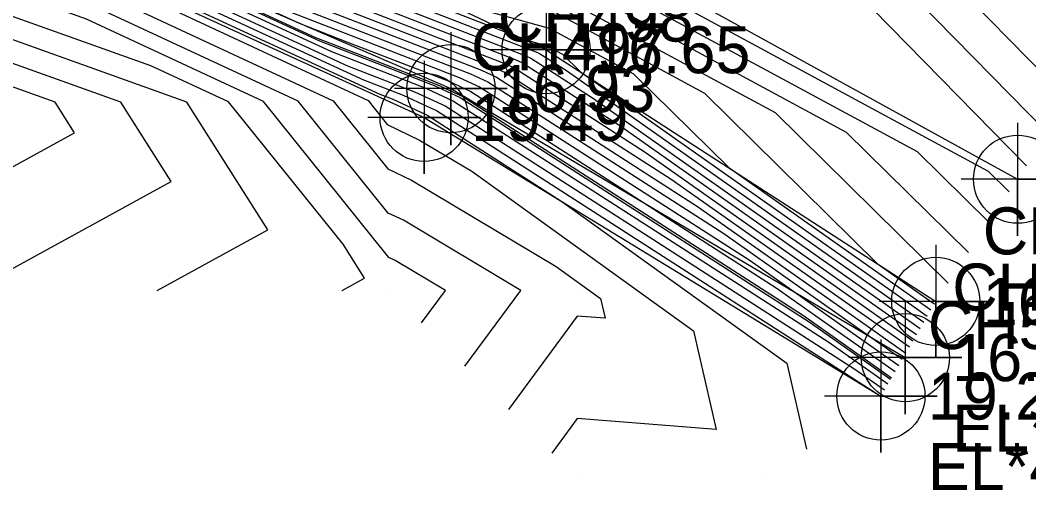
# Model space of a CAD drawing. Extents: x 2531902 to 2533249, y 715219 to 716099.
# Drawn here: x 2532970.4 to 2533024, y 715549.3 to 715574.4 of the extents above; entities that cross this region are included whole.
import ezdxf

# ---------------------------------------------------------------- set-up
doc = ezdxf.new("R2010")
doc.units = 0
for name, color, linetype in [('DTM Contours Major', 7, 'Continuous'), ('DTM Contours Minor', 7, 'Continuous'), ('Exist DTM Breakline', 7, 'Continuous'), ('Exist DTM Breakline Cogo Comment', 7, 'Continuous'), ('Exist DTM Breakline Cogo Elevation', 7, 'Continuous'), ('Exist DTM Breakline Cogo Number', 7, 'Continuous'), ('Exist DTM Breakline Cogo Point CELL', 7, 'Continuous'), ('Exist DTM Breakline Underwater', 7, 'Continuous'), ('Exist DTM Breakline Underwater Cogo Elevation', 7, 'Continuous'), ('Exist DTM Breakline Underwater Cogo Number', 7, 'Continuous'), ('Exist DTM Breakline Underwater Cogo Point CELL', 7, 'Continuous'), ('Exist DTM Drainline', 7, 'Continuous'), ('Exist DTM Drainline Cogo Point CELL', 7, 'Continuous'), ('Exist DTM QL2 LIDAR Elevation Point', 7, 'Continuous'), ('Exist Hydro Stream or Body of Water', 7, 'Continuous'), ('Scratch_Level_2', 7, 'Continuous')]:
    doc.layers.add(name, color=color, linetype=linetype)

msp = doc.modelspace()

# ---------------------------------------------------------------- linework, layer by layer
at = {"layer": 'DTM Contours Major'}
for points in [[(2532994.03, 715555.97), (2532996.996, 715560), (2532990.752, 715563.725), (2532989.952, 715564.108), (2532985.16, 715570.051), (2532970.453, 715576.899), (2532964.736, 715578.943), (2532963.003, 715576.997), (2532958.708, 715578.708), (2532955.803, 715580), (2532957.483, 715581.528), (2532947.518, 715585.016), (2532942.705, 715587.122), (2532940.418, 715590.138), (2532936.555, 715591.75), (2532925.398, 715596.429), (2532923.547, 715596.608), (2532919.889, 715598.604), (2532917.722, 715599.441)], [(2532957.968, 715560), (2532973.262, 715568.369), (2532972.222, 715570), (2532969.408, 715571.007), (2532969.212, 715570.788), (2532956.037, 715576.037), (2532950, 715578.722), (2532945.552, 715580), (2532940.791, 715582.083), (2532940, 715583.127), (2532932.731, 715590), (2532928.828, 715591.637), (2532921.27, 715592.366), (2532913.266, 715596.734), (2532915.617, 715590), (2532919.56, 715583.804)], [(2532951.849, 715588.22), (2532960.66, 715584.212), (2532964.098, 715582.854), (2532976.998, 715576.911), (2532987.781, 715571.944), (2532991.344, 715570.562), (2532992.164, 715570.184), (2532992.969, 715569.812), (2533003.774, 715562.875), (2533014.776, 715555.81), (2533016.344, 715554.707)], [(2532977.376, 715582.282), (2532982.374, 715580.345), (2532998.782, 715575.801), (2533010.54, 715569.447), (2533019.732, 715560.393)], [(2532976.033, 715580.934), (2532979.22, 715579.466), (2532996.217, 715572.876), (2532997.295, 715572.458), (2532997.539, 715572.346), (2533000.818, 715570.24), (2533016.733, 715559.04), (2533018.242, 715557.978)], [(2532973.983, 715580.089), (2532983.5, 715575.705), (2532990.196, 715573.109), (2532994.32, 715571.51), (2532995.254, 715571.079), (2533007.797, 715563.025), (2533014.067, 715558.613), (2533017.293, 715556.342)]]:
    msp.add_lwpolyline(points, dxfattribs=at)
at = {"layer": 'DTM Contours Minor'}
for points in [[(2533023.913, 715566.613), (2533023.884, 715566.643), (2533007.566, 715583.283), (2533002.168, 715586.347), (2533001.911, 715586.506), (2533000.454, 715587.404), (2532996.886, 715588.809), (2532975.24, 715591.229), (2532960.443, 715606.627)], [(2533025.081, 715568.308), (2533024.981, 715568.41), (2533013.199, 715580.426), (2533003.105, 715586.155), (2533002.625, 715586.451), (2532999.899, 715588.132), (2532993.228, 715590.758), (2532975.904, 715592.695), (2532964.062, 715605.019)], [(2533026.25, 715570.004), (2533026.079, 715570.178), (2533018.831, 715577.569), (2533004.043, 715585.963), (2533003.339, 715586.397), (2532999.345, 715588.86), (2532989.57, 715592.707), (2532976.568, 715594.161), (2532967.681, 715603.41)], [(2532967.811, 715560), (2532978.405, 715565.797), (2532975.725, 715570), (2532968.473, 715572.594), (2532967.971, 715572.029), (2532956.571, 715576.571), (2532950, 715579.494), (2532948.238, 715580), (2532941.174, 715583.091), (2532940, 715584.639), (2532934.331, 715590), (2532928.142, 715592.595), (2532921.725, 715593.214), (2532910.851, 715599.149), (2532914.045, 715590), (2532920, 715580.643), (2532921.07, 715580), (2532927.464, 715577.464), (2532930, 715577.182), (2532934.313, 715570), (2532940, 715561.698), (2532944.519, 715560), (2532947.972, 715557.972)], [(2532948.501, 715594.482), (2532971.061, 715585.571), (2532972.404, 715585.371), (2532973.629, 715585.494), (2532975.926, 715584.066), (2532999.05, 715577.662), (2533018.088, 715567.375), (2533021.897, 715563.623)], [(2532949.216, 715593.878), (2532972.623, 715584.632), (2532972.93, 715584.51), (2532974.083, 715583.979), (2532977.429, 715582.682), (2532998.916, 715576.732), (2533014.314, 715568.411), (2533020.814, 715562.008)], [(2532950.646, 715592.67), (2532970.768, 715584.721), (2532971.826, 715584.303), (2532975.795, 715582.475), (2532987.319, 715578.007), (2532998.647, 715574.87), (2533006.766, 715570.483), (2533015.958, 715561.428), (2533018.866, 715559.382), (2533019.002, 715559.286)], [(2532967.018, 715589.645), (2532974.992, 715590.446), (2532989.945, 715581.152), (2532999.185, 715578.593), (2533021.862, 715566.339), (2533022.979, 715565.239)], [(2532968.913, 715584.811), (2532970.722, 715584.096), (2532977.507, 715580.971), (2532997.208, 715573.333), (2532998.379, 715573.008), (2532999.218, 715572.555), (2533000.168, 715571.619), (2533017.8, 715559.211), (2533018.622, 715558.632)], [(2532969.841, 715584.766), (2532971.274, 715584.2), (2532976.651, 715581.723), (2532992.263, 715575.67), (2532998.513, 715573.939), (2533002.992, 715571.519), (2533008.063, 715566.524), (2533018.333, 715559.296), (2533018.812, 715558.959)], [(2532968.514, 715583.682), (2532980.932, 715577.962), (2532993.809, 715572.969), (2532996.105, 715572.079), (2532996.625, 715571.839), (2533003.61, 715567.354), (2533015.666, 715558.869), (2533017.863, 715557.324)], [(2532969.066, 715583.786), (2532980.076, 715578.714), (2532995.013, 715572.923), (2532996.7, 715572.269), (2532997.082, 715572.092), (2533002.214, 715568.797), (2533016.2, 715558.955), (2533018.052, 715557.651)], [(2532970.17, 715583.993), (2532978.363, 715580.218), (2532997.421, 715572.83), (2532997.89, 715572.648), (2532997.996, 715572.599), (2532999.422, 715571.683), (2533017.266, 715559.125), (2533018.432, 715558.305)], [(2532965.202, 715583.061), (2532986.069, 715573.448), (2532986.584, 715573.249), (2532992.534, 715570.942), (2532993.883, 715570.319), (2533011.985, 715558.696), (2533012.467, 715558.357), (2533016.723, 715555.361)], [(2532965.754, 715583.165), (2532985.213, 715574.2), (2532987.788, 715573.202), (2532993.129, 715571.131), (2532994.34, 715570.572), (2533010.589, 715560.139), (2533013, 715558.442), (2533016.913, 715555.688)], [(2532966.306, 715583.268), (2532984.357, 715574.953), (2532988.992, 715573.155), (2532993.724, 715571.321), (2532994.797, 715570.825), (2533009.193, 715561.582), (2533013.533, 715558.528), (2533017.103, 715556.015)], [(2532967.41, 715583.475), (2532982.644, 715576.457), (2532991.401, 715573.062), (2532994.915, 715571.7), (2532995.711, 715571.332), (2533006.401, 715564.468), (2533014.6, 715558.698), (2533017.483, 715556.669)], [(2532967.962, 715583.579), (2532981.788, 715577.209), (2532992.605, 715573.016), (2532995.51, 715571.89), (2532996.168, 715571.586), (2533005.005, 715565.911), (2533015.133, 715558.784), (2533017.673, 715556.997)], [(2532963.546, 715582.75), (2532971.692, 715578.998), (2532988.637, 715571.192), (2532990.749, 715570.373), (2532992.038, 715569.778), (2532992.512, 715569.559), (2532998.882, 715565.469), (2533015.963, 715554.501), (2533016.099, 715554.404), (2533016.111, 715554.352)], [(2532964.65, 715582.957), (2532982.303, 715574.825), (2532986.925, 715572.696), (2532991.939, 715570.752), (2532992.291, 715570.59), (2532993.426, 715570.065), (2533008.665, 715560.281), (2533013.38, 715557.253), (2533016.534, 715555.034)], [(2532963.584, 715581.862), (2532988.872, 715570.087), (2532989.898, 715568.815), (2532991.613, 715567.992), (2532994.386, 715566.338), (2533006.193, 715557.847), (2533007.391, 715552.609), (2533000, 715553.192), (2532998.647, 715551.353)], [(2532966.386, 715581.084), (2532989.493, 715570.439), (2532990.154, 715570.183), (2532991.911, 715569.372), (2532992.055, 715569.305), (2532993.991, 715568.062), (2532999.181, 715564.73), (2533011.146, 715556.125), (2533012.19, 715551.56)], [(2532967.019, 715579.38), (2532987.016, 715570.069), (2532989.925, 715566.461), (2532991.183, 715565.859), (2532998.876, 715561.269), (2533001.24, 715559.569), (2533001.48, 715558.52), (2533000, 715558.637), (2532996.338, 715553.662)], [(2532991.721, 715558.279), (2532992.988, 715560), (2532990.321, 715561.591), (2532989.98, 715561.755), (2532983.304, 715570.032), (2532973.887, 715574.417), (2532965.671, 715577.356)], [(2532987.497, 715560), (2532988.692, 715560.654), (2532987.541, 715562.459), (2532981.448, 715570.014), (2532977.322, 715571.935), (2532966.605, 715575.769)], [(2532977.654, 715560), (2532983.549, 715563.226), (2532979.229, 715570), (2532967.539, 715574.181)]]:
    msp.add_lwpolyline(points, dxfattribs=at)
at = {"layer": 'Exist DTM Breakline'}
msp.add_lwpolyline([(2532713.668, 715632.91), (2532738.883, 715624.395), (2532759.246, 715620.539), (2532773.868, 715619.638), (2532797.122, 715620.541), (2532830.298, 715626.45), (2532834.772, 715629.357), (2532845.901, 715630.257), (2532852.301, 715627.724), (2532853.675, 715626.881), (2532873.942, 715617.949), (2532888.735, 715612.988), (2532909.367, 715604.653), (2532924.285, 715597.984), (2532944.343, 715591.433), (2532962.6, 715582.573), (2532991.856, 715569.195), (2533016.156, 715554.384)], dxfattribs=at)
at = {"layer": 'Exist DTM Breakline Cogo Point CELL'}
for points in [[(2532993.283, 715573.726), (2532993.283, 715567.726), (2532993.283, 715570.726), (2532996.283, 715570.726), (2532990.283, 715570.726)], [(2532991.856, 715572.195), (2532991.856, 715566.195), (2532991.856, 715569.195), (2532994.856, 715569.195), (2532988.856, 715569.195)], [(2533017.454, 715559.427), (2533017.454, 715553.427), (2533017.454, 715556.427), (2533020.454, 715556.427), (2533014.454, 715556.427)], [(2533016.156, 715557.384), (2533016.156, 715551.384), (2533016.156, 715554.384), (2533019.156, 715554.384), (2533013.156, 715554.384)]]:
    msp.add_lwpolyline(points, dxfattribs=at)
for centre in [(2532993.283, 715570.726), (2532991.856, 715569.195), (2533017.454, 715556.427), (2533016.156, 715554.384)]:
    msp.add_circle(centre, 2.344, dxfattribs=at)
at = {"layer": 'Exist DTM Breakline Underwater'}
msp.add_lwpolyline([(2532642.404, 715750.56), (2532658.799, 715717.787), (2532669.356, 715695.376), (2532679.885, 715666.767), (2532697.228, 715643.446), (2532713.346, 715638.817), (2532732.829, 715632.464), (2532756.843, 715626.148), (2532779.072, 715626.28), (2532796.688, 715625.652), (2532823.757, 715631.859), (2532837.11, 715635.289), (2532855.521, 715634.196), (2532877.341, 715623.453), (2532903.322, 715612.979), (2532923.748, 715606.844), (2532938.002, 715599.697), (2532947.164, 715595.611), (2532973.382, 715584.595), (2532998.348, 715572.794), (2533019.077, 715559.415)], dxfattribs=at)
at = {"layer": 'Exist DTM Breakline Underwater Cogo Point CELL'}
for points in [[(2532998.348, 715575.794), (2532998.348, 715569.794), (2532998.348, 715572.794), (2533001.348, 715572.794), (2532995.348, 715572.794)], [(2533019.077, 715562.415), (2533019.077, 715556.415), (2533019.077, 715559.415), (2533022.077, 715559.415), (2533016.077, 715559.415)]]:
    msp.add_lwpolyline(points, dxfattribs=at)
for centre in [(2532998.348, 715572.794), (2533019.077, 715559.415)]:
    msp.add_circle(centre, 2.344, dxfattribs=at)
at = {"layer": 'Exist DTM Drainline'}
msp.add_lwpolyline([(2532712.089, 715642.317), (2532734.218, 715637.287), (2532753.576, 715632.211), (2532781.659, 715633.208), (2532801.91, 715635.068), (2532816.971, 715637.962), (2532839.573, 715644.872), (2532859.48, 715643.736), (2532879.315, 715631.66), (2532904.837, 715623.619), (2532925.407, 715612.713), (2532951.291, 715602.124), (2532975.159, 715591.05), (2532999.274, 715579.213), (2533023.429, 715565.909)], dxfattribs=at)
at = {"layer": 'Exist DTM Drainline Cogo Point CELL'}
msp.add_lwpolyline([(2533023.429, 715568.909), (2533023.429, 715562.909), (2533023.429, 715565.909), (2533026.429, 715565.909), (2533020.429, 715565.909)], dxfattribs=at)
msp.add_circle((2533023.429, 715565.909), 2.344, dxfattribs=at)
at = {"layer": 'Exist DTM QL2 LIDAR Elevation Point'}
for p, q in [((2532980, 715570), (2532980, 715570)), ((2532990, 715560), (2532990, 715560)), ((2533000, 715560), (2533000, 715560)), ((2533000, 715550), (2533000, 715550)), ((2533010, 715550), (2533010, 715550))]:
    msp.add_line(p, q, dxfattribs=at)
at = {"layer": 'Exist Hydro Stream or Body of Water'}
msp.add_lwpolyline([(2532965.064, 715583.035), (2532986.283, 715573.26), (2532992.386, 715570.894), (2532993.769, 715570.255), (2533012.334, 715558.335), (2533016.676, 715555.279)], dxfattribs=at)
at = {"layer": 'Scratch_Level_2'}
msp.add_lwpolyline([(2532714.664, 715634.736), (2532739.321, 715626.311), (2532759.871, 715623.13), (2532773.772, 715622.161), (2532797.407, 715622.564), (2532828.795, 715628.744), (2532834.22, 715630.983), (2532845.975, 715632.207), (2532853.028, 715629.31), (2532854.542, 715628.512), (2532875.028, 715620.214), (2532888.893, 715614.569), (2532909.676, 715606.722), (2532925.335, 715600.738), (2532945.352, 715592.461), (2532962.769, 715583.896), (2532993.283, 715570.726), (2533017.454, 715556.427)], dxfattribs=at)

# ---------------------------------------------------------------- texts
at = {"layer": 'Exist DTM Breakline Cogo Comment'}
for s, p in [('EL*4005A', (2533019.954, 715551.427)), ('EL*4005', (2533018.656, 715549.384))]:
    msp.add_text(s, height=2.5, dxfattribs=at).set_placement(p)
at = {"layer": 'Exist DTM Breakline Cogo Elevation'}
for s, p in [('16.93', (2532995.783, 715569.476)), ('19.49', (2532994.356, 715567.945)), ('16.83', (2533019.954, 715555.177)), ('19.20', (2533018.656, 715553.134))]:
    msp.add_text(s, height=2.5, dxfattribs=at).set_placement(p)
at = {"layer": 'Exist DTM Breakline Cogo Number'}
for s, p in [('CH498', (2532995.783, 715573.226)), ('CH497', (2532994.356, 715571.695)), ('CH499', (2533019.954, 715558.927)), ('CH500', (2533018.656, 715556.884))]:
    msp.add_text(s, height=2.5, dxfattribs=at).set_placement(p)
at = {"layer": 'Exist DTM Breakline Underwater Cogo Elevation'}
for s, p in [('16.65', (2533000.848, 715571.544)), ('16.12', (2533021.577, 715558.165))]:
    msp.add_text(s, height=2.5, dxfattribs=at).set_placement(p)
at = {"layer": 'Exist DTM Breakline Underwater Cogo Number'}
msp.add_text('CH647', height=2.5, dxfattribs=at).set_placement((2533021.577, 715561.915))

doc.saveas('drawing.dxf')
